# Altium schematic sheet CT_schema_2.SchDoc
size 335 x 238 mm
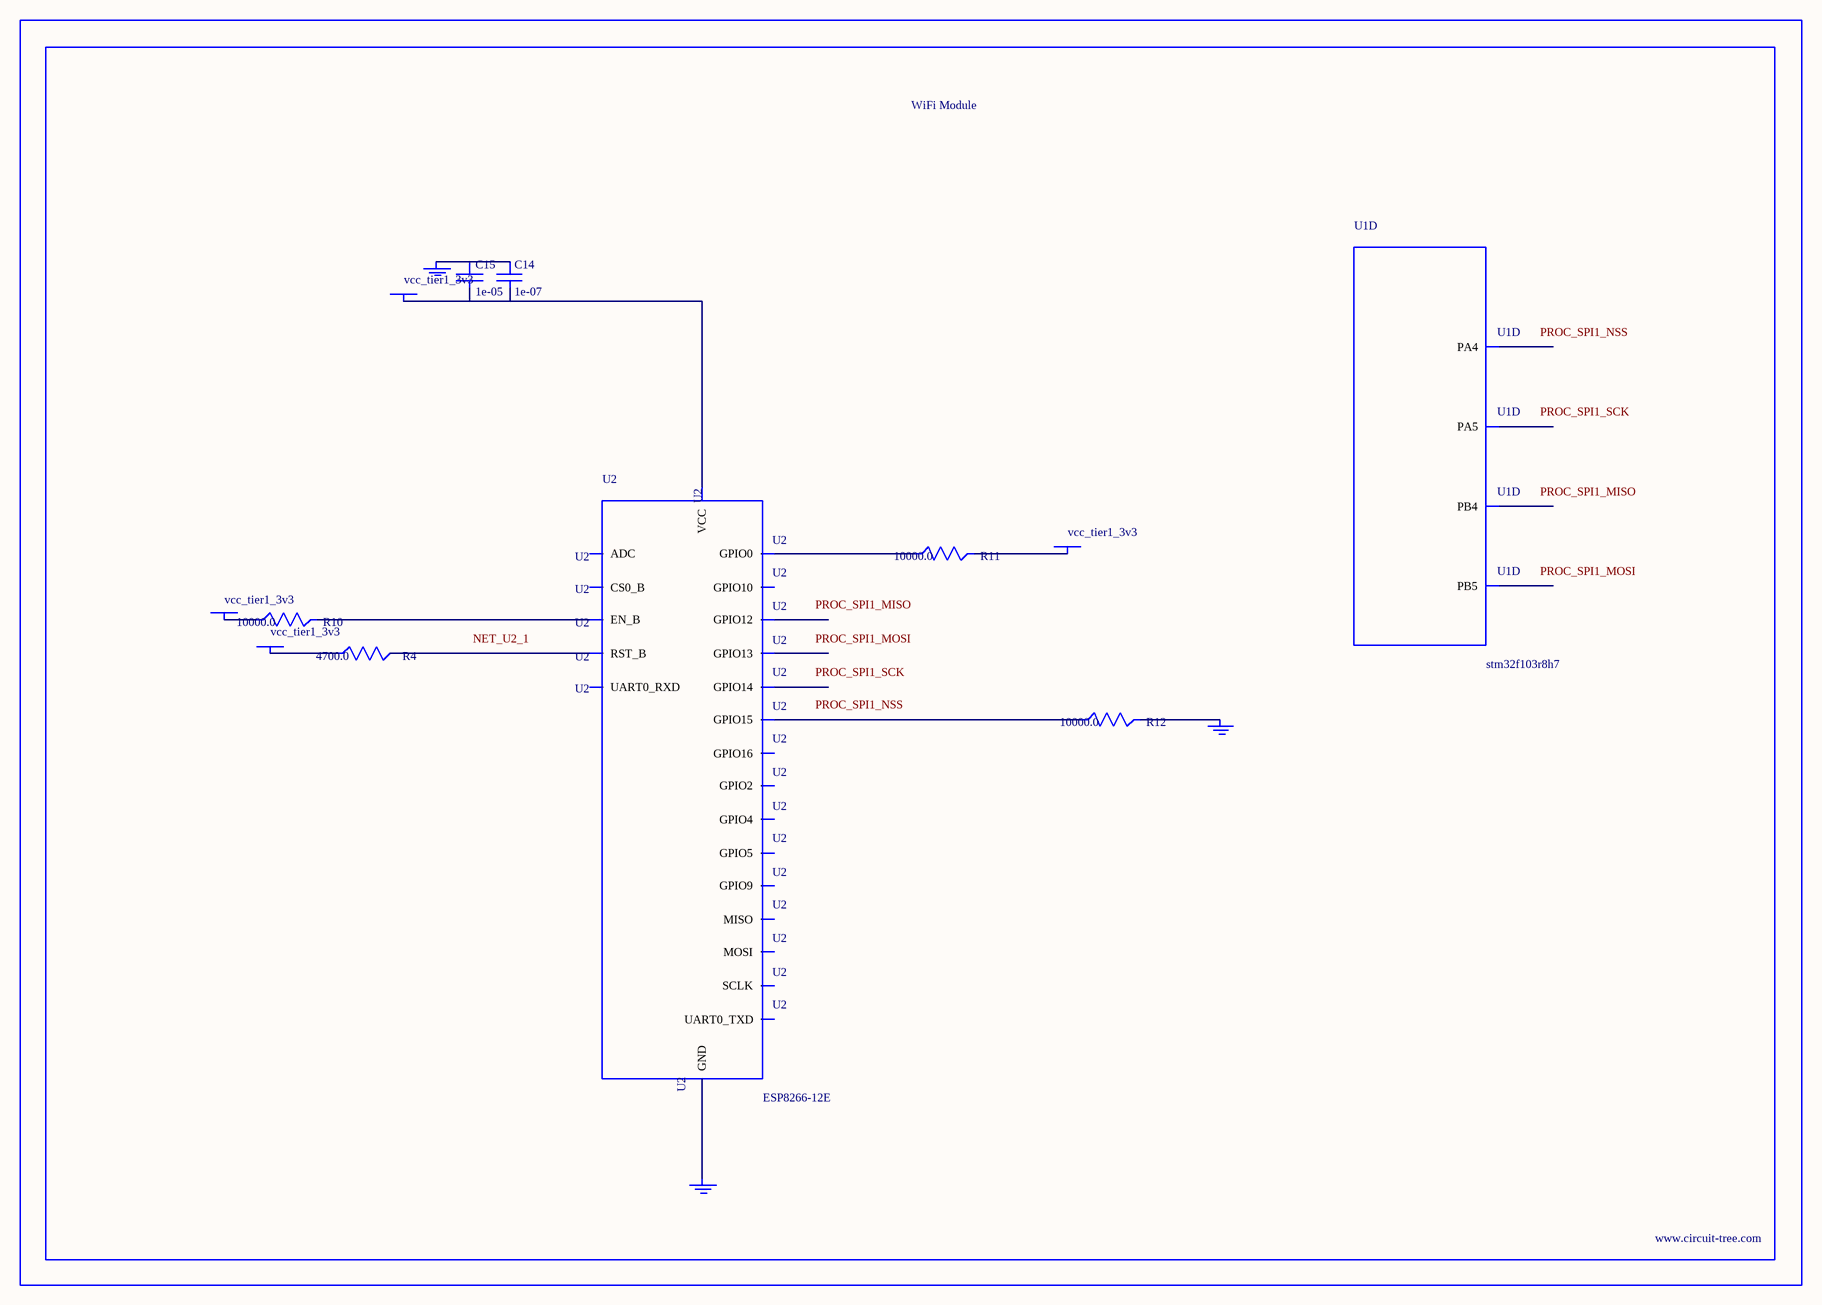
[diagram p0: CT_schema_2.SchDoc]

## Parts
BORDER1  (no value)
C14  1e-07  [C0402]
C15  1e-05  [C0805]
GND_INSTANCE_1_0  (no value)
GND_INSTANCE_1_1  (no value)
GND_INSTANCE_1_2  (no value)
POWER_INSTANCE_1_0  vcc_tier1_3v3
POWER_INSTANCE_1_1  vcc_tier1_3v3
POWER_INSTANCE_1_2  vcc_tier1_3v3
POWER_INSTANCE_1_3  vcc_tier1_3v3
R4  4700.0  [R0603]
R10  10000.0  [R0603]
R11  10000.0  [R0603]
R12  10000.0  [R0603]
U1  stm32f103r8h7  [TFBGA64]  (part D of 7)
U2  ESP8266-12E  [ESP8266-12E]

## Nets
NetC14_1: C14.1 C15.1 GND_INSTANCE_1_0.0(GND)
NetC14_2: C14.2 C15.2 POWER_INSTANCE_1_1.0(PWR) U2.8(VCC)
NetGND_INSTANCE_1_1_0: GND_INSTANCE_1_1.0(GND) R12.2
NetGND_INSTANCE_1_2_0: GND_INSTANCE_1_2.0(GND) U2.15(GND)
NetPOWER_INSTANCE_1_0_0: POWER_INSTANCE_1_0.0(PWR) R10.1
NetPOWER_INSTANCE_1_2_0: POWER_INSTANCE_1_2.0(PWR) R11.2
NetPOWER_INSTANCE_1_3_0: POWER_INSTANCE_1_3.0(PWR) R4.1
NetR4_2: R4.2 U2.1(RST_B)
NetR10_2: R10.2 U2.3(EN_B)
NetR11_1: R11.1 U2.18(GPIO0)
NetR12_1: R12.1 U2.16(GPIO15)

Not connected (* = marked no-connect by the designer): U1 A4(PB4) C4(PB5) F4(PA5) H3(PA4); U2 2(ADC) 4(GPIO16) 5(GPIO14) 6(GPIO12) 7(GPIO13) 9(CS0_B) 10(MISO) 11(GPIO9) 12(GPIO10) 13(MOSI) 14(SCLK) 17(GPIO2) 19(GPIO4) 20(GPIO5) 21(UART0_RXD) 22(UART0_TXD)

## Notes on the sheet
- Labels drawn without touching a wire or pin: NET_U2_1, PROC_SPI1_MISO, PROC_SPI1_MOSI, PROC_SPI1_NSS, PROC_SPI1_SCK

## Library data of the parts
BORDER1 = BORDER_PAGE1
C14 = C0402C104K3RACTU
C15 = C0805C106K8RACTU
GND_INSTANCE_1_0-GND_INSTANCE_1_2 = GND
POWER_INSTANCE_1_0-POWER_INSTANCE_1_3 = PWR
R4 = RC0603JR-074K7L
R10-R12 = RC0603JR-0710KL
